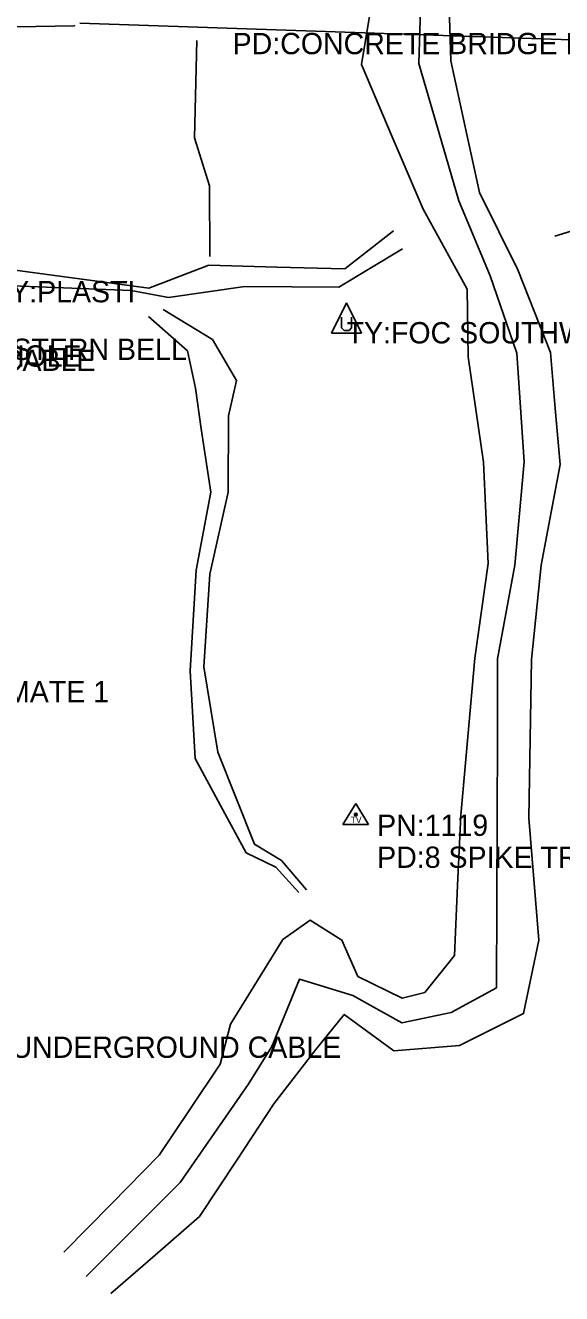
# Model space of a CAD drawing. Extents: x 976456 to 985170, y 1525951 to 1527080.
# Drawn here: x 977943.1 to 978068.8, y 1526186.9 to 1526484.4 of the extents above; entities that cross this region are included whole.
import ezdxf

# ---------------------------------------------------------------- set-up
doc = ezdxf.new("R2010")
doc.units = 0
for name, color, linetype in [('S_BRIDGE', 7, 'Continuous'), ('S_CROSS_DRAIN_ANNOT', 7, 'Continuous'), ('S_DITCHLINE', 7, 'Continuous'), ('S_GUARDRAIL', 7, 'Continuous'), ('S_MANHOLE_ANNOT', 7, 'Continuous'), ('S_PRIMARY_CTL_ANNOT', 7, 'Continuous'), ('S_RDW_PT_SYM', 7, 'Continuous'), ('S_SECONDARY_CTL', 7, 'Continuous'), ('S_SECONDARY_CTL_ANNOT', 7, 'Continuous'), ('S_STREAM', 7, 'Continuous'), ('S_UNDERGROUND_CABLE', 7, 'Continuous'), ('S_UTILITY_POLE_ANNOT', 7, 'Continuous')]:
    doc.layers.add(name, color=color, linetype=linetype)

msp = doc.modelspace()

# ---------------------------------------------------------------- linework, layer by layer
at = {"layer": 'S_BRIDGE'}
msp.add_line((977955.86, 1526484.94), (978085.38, 1526480.48), dxfattribs=at)
at = {"layer": 'S_DITCHLINE'}
for points in [[(977983.26, 1526480.85), (977982.7, 1526458.01), (977986.21, 1526446.78), (977986.29, 1526430.17)], [(978091.05, 1526442.31), (978067.19, 1526434.95)], [(978029.35, 1526436.22), (978017.97, 1526427.26), (978002.04, 1526427.7), (977986.11, 1526428.13), (977972.06, 1526422.75), (977955.81, 1526424.94), (977939.55, 1526427.12), (977915.43, 1526423.73), (977894.67, 1526425.09), (977873.2, 1526426.21), (977862.22, 1526427.92)], [(977861.21, 1526423.15), (977872.89, 1526423.19), (977894, 1526421.24), (977915.17, 1526420.65), (977936.11, 1526423.49), (977952.01, 1526422.85), (977967.92, 1526422.22), (977976.62, 1526420.59), (977994.52, 1526423.18), (978016.54, 1526422.99), (978031.46, 1526432.01)], [(977975.38, 1526417.73), (977986.92, 1526410.75), (977992.57, 1526401.12), (977990.72, 1526392.85), (977990.64, 1526374.89), (977986.36, 1526355.72), (977984.89, 1526333.95), (977988.17, 1526313.91), (977996.81, 1526292.35), (978003.11, 1526288.54), (978009, 1526281.61)], [(977971.98, 1526416.14), (977981.12, 1526408.05), (977982.97, 1526399.31), (977984.29, 1526389.74), (977986.56, 1526374.9), (977983.13, 1526356.6), (977981.73, 1526332.99), (977982.86, 1526312.44), (977988.86, 1526301.4), (977994.86, 1526290.36), (978001.82, 1526286.99), (978007.2, 1526281.04)]]:
    msp.add_lwpolyline(points, dxfattribs=at)
at = {"layer": 'S_GUARDRAIL'}
msp.add_line((977928.47, 1526483.86), (977954.58, 1526484.3), dxfattribs=at)
at = {"layer": 'S_RDW_PT_SYM'}
msp.add_lwpolyline([(977954.58, 1526484.3), (977954.58, 1526484.35), (977954.58, 1526484.3), (977954.53, 1526484.3), (977954.58, 1526484.3), (977954.58, 1526484.25), (977954.58, 1526484.3), (977954.63, 1526484.3)], dxfattribs=at)
at = {"layer": 'S_SECONDARY_CTL'}
for p, q in [((978020.53, 1526301.91), (978017.52, 1526296.95)), ((978020.53, 1526301.91), (978023.47, 1526296.95)), ((978017.52, 1526296.95), (978023.47, 1526296.95))]:
    msp.add_line(p, q, dxfattribs=at)
for radius in [0.311, 0.183, 0.103]:
    msp.add_circle((978020.53, 1526299.3), radius, dxfattribs=at)
at = {"layer": 'S_STREAM'}
for points in [[(977952.1, 1526196.63), (977963.27, 1526208.01), (977974.44, 1526219.38), (977981.61, 1526230.09), (977988.78, 1526240.79), (977991.16, 1526250.18), (978003.43, 1526269.97), (978009.83, 1526274.52), (978017.26, 1526269.86), (978021.03, 1526261.36), (978031.39, 1526256.24), (978036.67, 1526257.59), (978043.66, 1526266.22), (978044.39, 1526282.68), (978045.12, 1526299.14), (978046.76, 1526317.56), (978048.4, 1526335.98), (978051.57, 1526358.19), (978050.49, 1526381.93), (978048.66, 1526394.3), (978046.83, 1526406.67), (978046.61, 1526422.51), (978036.3, 1526441.3), (978029.08, 1526458.27), (978021.86, 1526475.24), (978025.61, 1526497.86)], [(977957.32, 1526190.94), (977968.34, 1526201.98), (977979.35, 1526213.01), (977987.34, 1526224.49), (977995.33, 1526235.96), (978000.87, 1526244.88), (978007.31, 1526260.71), (978019.84, 1526256.89), (978031.29, 1526250.44), (978042.87, 1526252.86), (978053.49, 1526258.69), (978053.59, 1526278.8), (978053.69, 1526298.91), (978053.71, 1526317.38), (978053.73, 1526335.86), (978057.82, 1526357.77), (978059.96, 1526382.06), (978059.11, 1526394.8), (978058.27, 1526407.55), (978052.01, 1526425.62), (978044.71, 1526443.26), (978040, 1526459.34), (978035.3, 1526475.42), (978036, 1526498.48)], [(977963.15, 1526186.94), (977973.54, 1526195.99), (977983.93, 1526205.04), (977992.63, 1526218.27), (978001.34, 1526231.49), (978011.2, 1526244.21), (978017.82, 1526252.37), (978029.44, 1526243.89), (978044.82, 1526245.15), (978059.86, 1526252.63), (978063.42, 1526269.86), (978062.24, 1526284.15), (978061.05, 1526298.45), (978061.39, 1526317.06), (978061.72, 1526335.67), (978064, 1526357.8), (978068.44, 1526381.43), (978067.28, 1526394.55), (978066.12, 1526407.67), (978058.53, 1526427.09), (978049.48, 1526445.16), (978046.12, 1526460.6), (978042.77, 1526476.04), (978042.11, 1526498.99)]]:
    msp.add_lwpolyline(points, dxfattribs=at)
at = {"layer": 'S_UNDERGROUND_CABLE'}
for p, q in [((978018.37, 1526419.33), (978014.84, 1526412.24)), ((978018.37, 1526419.33), (978021.86, 1526412.24)), ((978017.17, 1526413.48), (978017.17, 1526415.92)), ((978017.79, 1526412.82), (978017.17, 1526413.48)), ((978019.53, 1526413.48), (978018.99, 1526412.82)), ((978019.53, 1526415.92), (978019.53, 1526413.48)), ((978014.84, 1526412.24), (978021.86, 1526412.24)), ((978018.99, 1526412.82), (978017.79, 1526412.82))]:
    msp.add_line(p, q, dxfattribs=at)

# ---------------------------------------------------------------- texts
at = {"layer": 'S_CROSS_DRAIN_ANNOT'}
for s, p in [('INVERT OF PIPE DI:24" TY:PLASTI', (977860.63, 1526419.44)), ('INVERT OF PIPE DI:APPROXIMATE 1', (977845.69, 1526325.63))]:
    msp.add_text(s, height=5, dxfattribs=at).set_placement(p)
at = {"layer": 'S_MANHOLE_ANNOT'}
msp.add_text('BOTTOM OF MANHOLE', height=5, dxfattribs=at).set_placement((977881.61, 1526404.35))
at = {"layer": 'S_PRIMARY_CTL_ANNOT'}
msp.add_text('PD:CONCRETE BRIDGE END CHISELED SQUARE', height=5, dxfattribs=at).set_placement((977991.67, 1526477.63))
at = {"layer": 'S_SECONDARY_CTL'}
msp.add_text('TV', height=1.5, rotation=360, dxfattribs=at).set_placement((978019.32, 1526297.29))
at = {"layer": 'S_SECONDARY_CTL_ANNOT'}
for s, p in [('PN:1119', (978025.53, 1526294.3)), ('PD:8 SPIKE TRIG ELEV', (978025.53, 1526286.8))]:
    msp.add_text(s, height=5, dxfattribs=at).set_placement(p)
at = {"layer": 'S_UTILITY_POLE_ANNOT'}
for s, p in [('TY:FOC SOUTHWESTERN BELL', (978018.37, 1526409.8)), ('TY:FOC SOUTHWESTERN BELL', (977879.51, 1526405.92)), ('TY:UNDERGROUND CABLE', (977871.84, 1526403.35)), ('TY:UNDERGROUND CABLE', (977929.44, 1526242.24))]:
    msp.add_text(s, height=5, dxfattribs=at).set_placement(p)

doc.saveas('drawing.dxf')
